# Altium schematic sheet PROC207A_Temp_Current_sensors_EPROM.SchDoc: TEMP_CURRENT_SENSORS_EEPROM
size 431 x 279 mm; Date: Not shown in title block; ApprovedBy: Not shown in title block; CheckedBy: Not shown in title block; Author: Not shown in title block; CompanyName: Not shown in title block; DrawnBy: Mistral; Engineer: Not shown in title block; Organization: Not shown in title block; Address1: Not shown in title block; Address2: Not shown in title block; Address3: Not shown in title block; Address4: Not shown in title block; DocumentNumber: 8; Revision: Use project parameter SCH_Rev; SheetNumber: 9; SheetTotal: 18; PageSetup: Record=PageOptions¦CenterHorizontal=True¦CenterVertical=True¦PrintScale=1.00¦XCorrection=1.00¦YCorrection=1.00¦PrintKind=0¦BorderSize=5000000¦LeftOffset=0¦BottomOffset=0¦Orientation=2¦PaperLength=1000¦PaperWidth=1000¦Scale=100¦PaperSource=15¦PrintQuality=600¦MediaType=1¦DitherType=10¦PaperKind=Letter¦PrintScaleMode=1
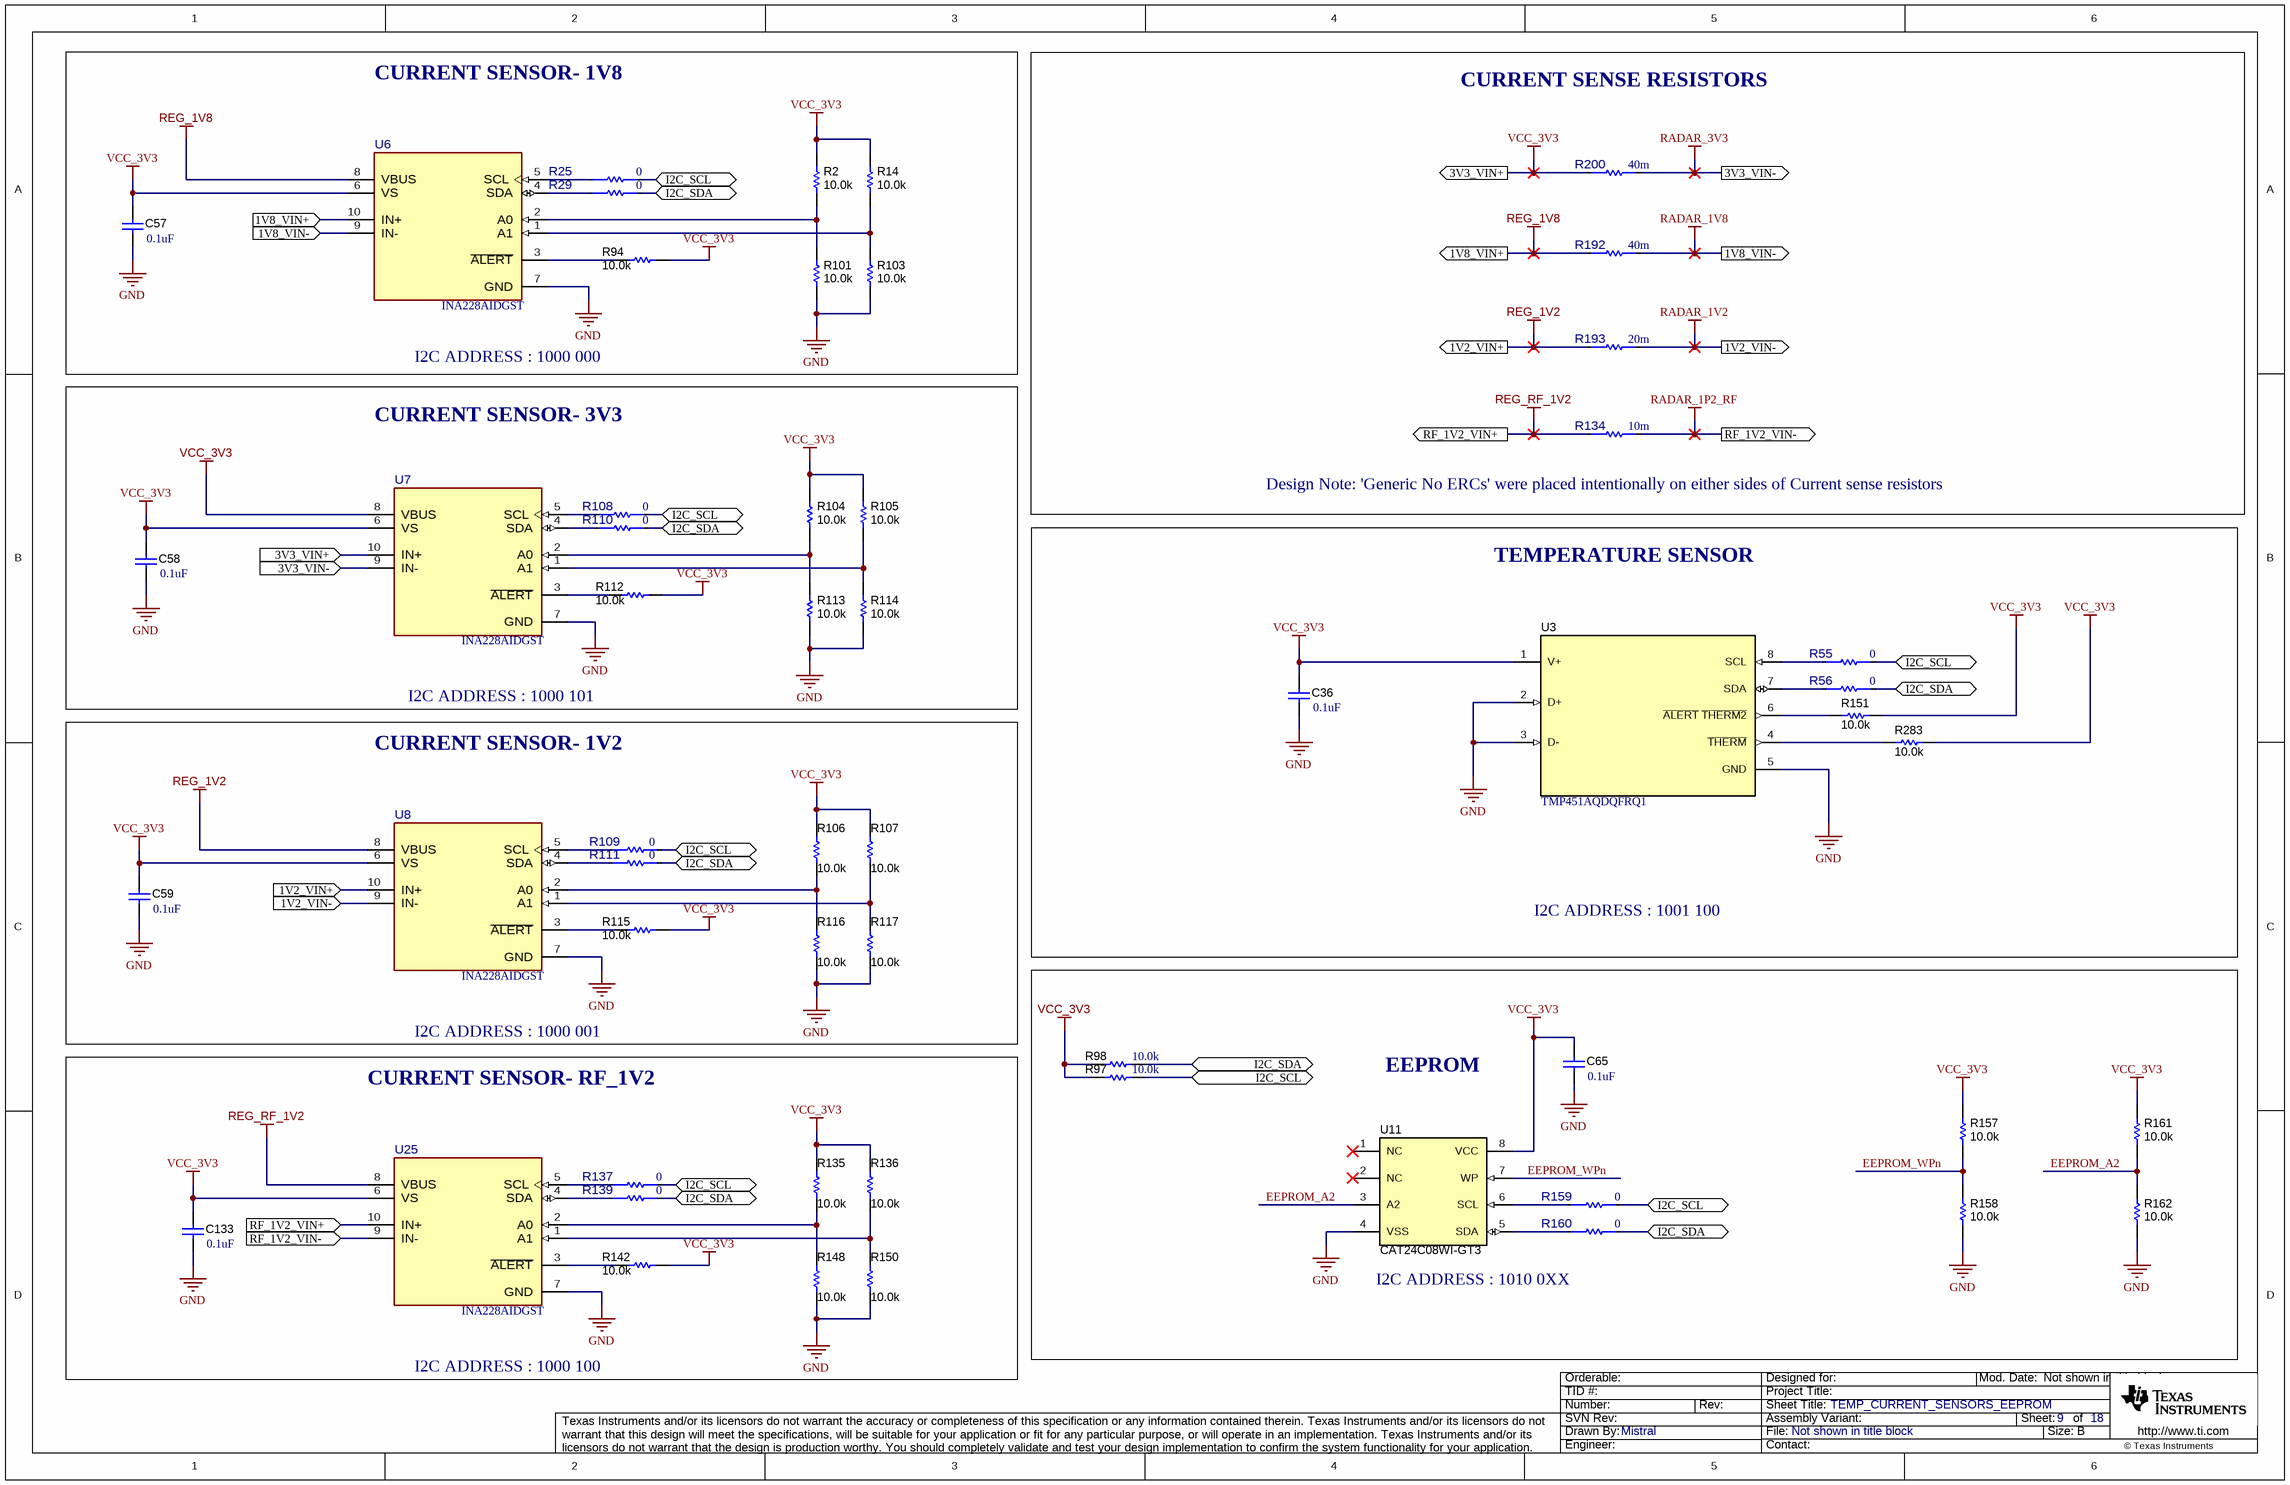
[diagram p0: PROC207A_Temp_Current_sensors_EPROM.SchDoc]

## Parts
C36  ValueDisplayed: 0.1uF  [0402]  (hidden comment: GCM155R71H104KE02D)
C57  ValueDisplayed: 0.1uF  [0402]  (hidden comment: GCM155R71H104KE02D)
C58  ValueDisplayed: 0.1uF  [0402]  (hidden comment: GCM155R71H104KE02D)
C59  ValueDisplayed: 0.1uF  [0402]  (hidden comment: GCM155R71H104KE02D)
C65  ValueDisplayed: 0.1uF  [0402]  (hidden comment: GCM155R71H104KE02D)
C133  ValueDisplayed: 0.1uF  [0402]  (hidden comment: GCM155R71H104KE02D)
R2  ValueDisplayed: 10.0k  [0402L]  (hidden comment: CRCW040210K0FKED)
R14  ValueDisplayed: 10.0k  [0402L]  (hidden comment: CRCW040210K0FKED)
R25  value 0  [FP-ERJ-2GE0R00X_0402-MFG]  (hidden comment: ERJ-2GE0R00X)
R29  value 0  [FP-ERJ-2GE0R00X_0402-MFG]  (hidden comment: ERJ-2GE0R00X)
R55  value 0  [FP-ERJ-2GE0R00X_0402-MFG]  (hidden comment: ERJ-2GE0R00X)
R56  value 0  [FP-ERJ-2GE0R00X_0402-MFG]  (hidden comment: ERJ-2GE0R00X)
R94  ValueDisplayed: 10.0k  [0402L]  (hidden comment: CRCW040210K0FKED)
R97  ValueDisplayed: 10.0k  [0402L]  (hidden comment: CRCW040210K0FKED)
R98  ValueDisplayed: 10.0k  [0402L]  (hidden comment: CRCW040210K0FKED)
R101  ValueDisplayed: 10.0k  [0402L]  (hidden comment: CRCW040210K0FKED)
R103  ValueDisplayed: 10.0k  [0402L]  (hidden comment: CRCW040210K0FKED)
R104  ValueDisplayed: 10.0k  [0402L]  (hidden comment: CRCW040210K0FKED)
R105  ValueDisplayed: 10.0k  [0402L]  (hidden comment: CRCW040210K0FKED)
R106  ValueDisplayed: 10.0k  [0402L]  (hidden comment: CRCW040210K0FKED)
R107  ValueDisplayed: 10.0k  [0402L]  (hidden comment: CRCW040210K0FKED)
R108  value 0  [FP-ERJ-2GE0R00X_0402-MFG]  (hidden comment: ERJ-2GE0R00X)
R109  value 0  [FP-ERJ-2GE0R00X_0402-MFG]  (hidden comment: ERJ-2GE0R00X)
R110  value 0  [FP-ERJ-2GE0R00X_0402-MFG]  (hidden comment: ERJ-2GE0R00X)
R111  value 0  [FP-ERJ-2GE0R00X_0402-MFG]  (hidden comment: ERJ-2GE0R00X)
R112  ValueDisplayed: 10.0k  [0402L]  (hidden comment: CRCW040210K0FKED)
R113  ValueDisplayed: 10.0k  [0402L]  (hidden comment: CRCW040210K0FKED)
R114  ValueDisplayed: 10.0k  [0402L]  (hidden comment: CRCW040210K0FKED)
R115  ValueDisplayed: 10.0k  [0402L]  (hidden comment: CRCW040210K0FKED)
R116  ValueDisplayed: 10.0k  [0402L]  (hidden comment: CRCW040210K0FKED)
R117  ValueDisplayed: 10.0k  [0402L]  (hidden comment: CRCW040210K0FKED)
R134  value 10m  [FP-WSL1206R0100FEB_1206-MFG]  (hidden comment: WSL1206R0100FEB)
R135  ValueDisplayed: 10.0k  [0402L]  (hidden comment: CRCW040210K0FKED)
R136  ValueDisplayed: 10.0k  [0402L]  (hidden comment: CRCW040210K0FKED)
R137  value 0  [FP-ERJ-2GE0R00X_0402-MFG]  (hidden comment: ERJ-2GE0R00X)
R139  value 0  [FP-ERJ-2GE0R00X_0402-MFG]  (hidden comment: ERJ-2GE0R00X)
R142  ValueDisplayed: 10.0k  [0402L]  (hidden comment: CRCW040210K0FKED)
R148  ValueDisplayed: 10.0k  [0402L]  (hidden comment: CRCW040210K0FKED)
R150  ValueDisplayed: 10.0k  [0402L]  (hidden comment: CRCW040210K0FKED)
R151  ValueDisplayed: 10.0k  [0402L]  (hidden comment: CRCW040210K0FKED)
R157  ValueDisplayed: 10.0k  [0402L]  (hidden comment: CRCW040210K0FKED)
R158  ValueDisplayed: 10.0k  [0402L]  (hidden comment: CRCW040210K0FKED)
R159  value 0  [FP-ERJ-2GE0R00X_0402-MFG]  (hidden comment: ERJ-2GE0R00X)
R160  value 0  [FP-ERJ-2GE0R00X_0402-MFG]  (hidden comment: ERJ-2GE0R00X)
R161  ValueDisplayed: 10.0k  [0402L]  (hidden comment: CRCW040210K0FKED)
R162  ValueDisplayed: 10.0k  [0402L]  (hidden comment: CRCW040210K0FKED)
R192  value 40m  [FP-WSL1206R0400FEB_1206-MFG]  (hidden comment: WSL1206R0400FEB)
R193  value 20m  [FP-WSL1206R0200FEB_1206-MFG]  (hidden comment: WSL1206R0200FEB)
R200  value 40m  [FP-WSL1206R0400FEB_1206-MFG]  (hidden comment: WSL1206R0400FEB)
R283  ValueDisplayed: 10.0k  [0402L]  (hidden comment: CRCW040210K0FKED)
U3  TMP451AQDQFRQ1  [DQF0008A]
U6  INA228AIDGST  [DGS0010A-MFG]
U7  INA228AIDGST  [DGS0010A-MFG]
U8  INA228AIDGST  [DGS0010A-MFG]
U11  CAT24C08WI-GT3  [SOIC-8]
U25  INA228AIDGST  [DGS0010A-MFG]

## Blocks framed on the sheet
CURRENT SENSOR- 1V8: C57 R2 R14 R25 R29 R94 R101 R103 U6
CURRENT SENSE RESISTORS: R134 R192 R193 R200
CURRENT SENSOR- 3V3: C58 R104 R105 R108 R110 R112-R114 U7
TEMPERATURE SENSOR: C36 R55 R56 R151 R283 U3
CURRENT SENSOR- 1V2: C59 R106 R107 R109 R111 R115-R117 U8
EEPROM: C65 R97 R98 R157-R162 U11
CURRENT SENSOR- RF_1V2: C133 R135-R137 R139 R142 R148 R150 U25

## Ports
1V2_VIN+ (in), 1V2_VIN+ (out), 1V2_VIN- (in), 1V2_VIN- (out), 1V8_VIN+ (in), 1V8_VIN+ (out), 1V8_VIN- (in), 1V8_VIN- (out), 3V3_VIN+ (in), 3V3_VIN+ (out), 3V3_VIN- (in), 3V3_VIN- (out), I2C_SCL (bidir), I2C_SDA (bidir), RF_1V2_VIN+ (in), RF_1V2_VIN+ (out), RF_1V2_VIN- (in), RF_1V2_VIN- (out)

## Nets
GND: C36.2 C57.2 C58.2 C59.2 C65.2 C133.2 R101.1 R103.1 R113.1 R114.1 R116.1 R117.1 R148.1 R150.1 R158.1 R162.1 U3.2(D+) U3.3(D-) U3.5(GND) U6.7(GND) U7.7(GND) U8.7(GND) U11.4(VSS) U25.7(GND)
RADAR_1P2_RF: R134.2 U25.9(IN-) ; port RF_1V2_VIN-
RADAR_1V2: R193.2 U8.9(IN-) ; port 1V2_VIN-
RADAR_1V8: R192.2 U6.9(IN-) ; port 1V8_VIN-
RADAR_3V3: R200.2 U7.9(IN-) ; port 3V3_VIN-
REG_1V2: R193.1 U8.8(VBUS) U8.10(IN+) ; port 1V2_VIN+
REG_1V8: R192.1 U6.8(VBUS) U6.10(IN+) ; port 1V8_VIN+
REG_RF_1V2: R134.1 U25.8(VBUS) U25.10(IN+) ; port RF_1V2_VIN+
VCC_3V3: C36.1 C57.1 C58.1 C59.1 C65.1 C133.1 R2.2 R14.2 R94.1 R97.2 R98.2 R104.2 R105.2 R106.2 R107.2 R112.1 R115.1 R135.2 R136.2 R142.1 R151.1 R157.2 R161.2 R200.1 R283.1 U3.1(V+) U6.6(VS) U7.6(VS) U7.8(VBUS) U7.10(IN+) U8.6(VS) U11.8(VCC) U25.6(VS) ; port 3V3_VIN+
EEPROM_A2: R161.1 R162.2 U11.3(A2)
EEPROM_WPn: R157.1 R158.2 U11.7(WP)
I2C_SCL: R25.2 R55.2 R97.1 R108.2 R109.2 R137.2 R159.2 ; port I2C_SCL
I2C_SDA: R29.2 R56.2 R98.1 R110.2 R111.2 R139.2 R160.2 ; port I2C_SDA
NetR2_1: R2.1 R101.2 U6.2(A0)
NetR14_1: R14.1 R103.2 U6.1(A1)
NetR25_1: R25.1 U6.5(SCL)
NetR29_1: R29.1 U6.4(SDA)
NetR55_1: R55.1 U3.8(SCL)
NetR56_1: R56.1 U3.7(SDA)
NetR94_2: R94.2 U6.3(~{ALERT})
NetR104_1: R104.1 R113.2 U7.2(A0)
NetR105_1: R105.1 R114.2 U7.1(A1)
NetR106_1: R106.1 R116.2 U8.2(A0)
NetR107_1: R107.1 R117.2 U8.1(A1)
NetR108_1: R108.1 U7.5(SCL)
NetR109_1: R109.1 U8.5(SCL)
NetR110_1: R110.1 U7.4(SDA)
NetR111_1: R111.1 U8.4(SDA)
NetR112_2: R112.2 U7.3(~{ALERT})
NetR115_2: R115.2 U8.3(~{ALERT})
NetR135_1: R135.1 R148.2 U25.2(A0)
NetR136_1: R136.1 R150.2 U25.1(A1)
NetR137_1: R137.1 U25.5(SCL)
NetR139_1: R139.1 U25.4(SDA)
NetR142_2: R142.2 U25.3(~{ALERT})
NetR151_2: R151.2 U3.6(~{ALERT}_~{THERM2})
NetR159_1: R159.1 U11.6(SCL)
NetR160_1: R160.1 U11.5(SDA)
NetR283_2: R283.2 U3.4(~{THERM})

Not connected (* = marked no-connect by the designer): U11 1(NC)* 2(NC)*

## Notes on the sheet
- I2C ADDRESS : 1000 000
- (near R134) Design Note: 'Generic No ERCs' were placed intentionally on either sides of Current sense resistors
- I2C ADDRESS : 1000 101
- I2C ADDRESS : 1001 100
- I2C ADDRESS : 1000 001
- I2C ADDRESS : 1010 0XX
- I2C ADDRESS : 1000 100

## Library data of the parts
C36 C57-C59 C65 C133 = CMP-0006356-2: CAP, CERM, 0.1 uF, 50 V, +/- 10%, X7R, AEC-Q200 Grade 1, 0402; Manufacturer: MuRata; TaMin_C: -55°C; Polarized: N; SizeAreaWB_mm2: 3; Value1: Unknown; U/M: EA; Value: 0.1uF; TaMax_C: 125°C; SizeZ_mm: 0.6; SizeX_mm: 1; SizeY_mm: 0.5; Value2: 50V; AEC Qualified: Y; Cap_F: 100nF; AEC Category: Q200
R2 R14 R94 R97 R98 R101 R103-R107 R112-R117 R135 R136 R142 R148 R150 R151 R157 R158 R161 R162 R283 = CMP-0025958-3: RES, 10.0 k, 1%, 0.063 W, AEC-Q200 Grade 0, 0402; Manufacturer: Vishay-Dale; Power_W: 63mW; TempCo: 100 ppm/C; Value_Code: 10k0; Value: 10.0k; EIA_Code: E96; Res_ohm: 10k; SizeX_mm: 1; SizeY_mm: 0.5; SizeZ_mm: 0.6; Value2: 0.063W; AEC Qualified: Y; VDC_V: 50V; AEC Category: Q200; AEC Grade: 0
R25 R29 R55 R56 R108-R111 R137 R139 R159 R160 = CMP-0002710-1: 0 Ohms Jumper Chip Resistor 0402 (1005 Metric) Automotive AEC-Q200 Thick Film; Manufacturer: Panasonic; SizeZ_mm: 0.4mm; AEC Qualified: Yes; AEC Grade: Grade 0; Power: 100mW
R134 = CMP-0121430-1: 10 mOhms ±1% 0.25W, 1/4W Chip Resistor Automotive AEC-Q200, Current Sense, Moisture Resistant, Pulse Withstanding Metal Element; Manufacturer: Vishay Dale; AEC Grade: Grade 0; AEC Qualified: Yes; Power_W: 250mW; SizeZ_mm: 0.889mm; TempCo: 75ppm/°C; Category 5A00970A6D5C81C7: Uncategorized; Category 5C6A91606D4187Ad: Resistors; Category 7542B8484461Ae85: Passive Components; Category Cd01000Bfc2916C6: Single Components; Voltage: 50mV
R192 R200 = CMP-0098431-1: 40 mOhms ±1% 0.25W, 1/4W Chip Resistor Automotive AEC-Q200, Current Sense, Moisture Resistant, Pulse Withstanding Metal Element; Manufacturer: Vishay; AEC Grade: Grade 0; AEC Qualified: Yes; Power_W: 250mW; SizeZ_mm: 0.889mm; TempCo: 75ppm/°C
R193 = CMP-0098430-1: Res Metal Strip 1206 0.02 Ohm 1% 1/4W ±75ppm/°C Molded SMD SMD T/R; Manufacturer: Vishay Dale; AEC Grade: Grade 0; AEC Qualified: Yes; Power_W: 250mW; SizeZ_mm: 0.889mm; Category 5C6A91606D4187Ad: Resistors; Category 7542B8484461Ae85: Passive Components; Category Cd01000Bfc2916C6: Single Components
U3 = CMP-0074317-1: Automotive Grade, 1.7V Remote and Local Temp Sensor with N-Factor, Filtering and Series-R Correction, DQF0008A (WSON-8); Alternate Manufacturer: Texas Instruments; SizeAreaWB_mm2: 9.0; U/M: EA; SizeZ_mm: 0.8; SizeX_mm: 2.0; SizeArea_mm2: 4.0; CompType: IC
U6-U8 U25 = CMP-0098432-1: Current Sense Amplifier 1 Circuit 10-VSSOP; Manufacturer: Texas Instruments; SizeZ_mm: 1.1mm; AEC Qualified: No; Input Bias Current: 0.01uA; Input Offset Voltage: 1mV; Max Supply Voltage: 5.5V; Min Supply Voltage: 2.7V; Nominal Supply Current: 640uA; Number Of Channels: 1; Standoff Height: 0.05mm; TaMax_C: +125°C; TaMin_C: -40°C; TJmax_C: +150°C
U11 = CMP-0005309-2: IC, EEPROM, 8KBIT, 400KHZ, 8SOIC; Manufacturer: ON Semiconductor; SizeAreaWB_mm2: 55.131; SizeZ_mm: 1.75; SizeX_mm: 5.99; SizeY_mm: 4.9; SizeArea_mm2: 29.351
